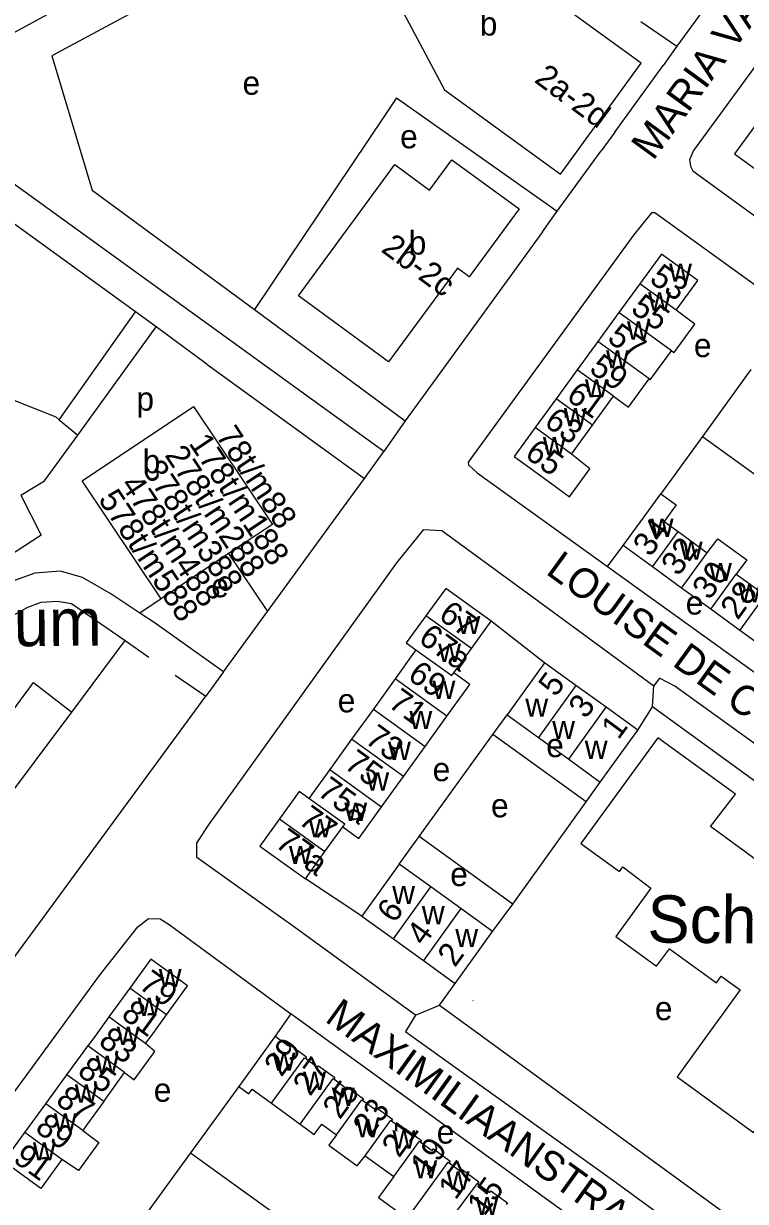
# Model space of a CAD drawing. Extents: x 159700 to 161346, y 381730 to 382922.
# Drawn here: x 159989.4 to 160111.3, y 382405.4 to 382604.4 of the extents above; entities that cross this region are included whole.
import ezdxf

# ---------------------------------------------------------------- set-up
doc = ezdxf.new("R2010")
doc.units = 0
for name, color, linetype in [('BLT_Basislijn', 7, 'Continuous'), ('BLT_Bebouwing', 7, 'Continuous'), ('BLT_Bebouwing_beschrifting', 7, 'Continuous'), ('BLT_Centroide', 7, 'Continuous'), ('BLT_Huisnummer', 7, 'Continuous'), ('BLT_Huisnummer_ tussenligend', 7, 'Continuous'), ('BLT_Huisnummer_reeks', 7, 'Continuous'), ('BLT_Onderverdeling_panden', 7, 'Continuous'), ('BLT_Straatnaam', 7, 'Continuous')]:
    doc.layers.add(name, color=color, linetype=linetype)

msp = doc.modelspace()

# ---------------------------------------------------------------- linework, layer by layer
at = {"layer": 'BLT_Basislijn'}
for p, q in [((160130.3, 382642.41), (160099.71, 382600.64)), ((160093.66, 382604.8), (160099.71, 382600.64)), ((160099.71, 382600.64), (160097.4, 382597.35)), ((160089.23, 382586.09), (160097.4, 382597.35)), ((160052.37, 382591.91), (160050.31, 382588.83)), ((160052.37, 382591.91), (160079.52, 382572.72)), ((160050.31, 382588.83), (160028.35, 382556.13)), ((160050.2, 382532.12), (159974.86, 382586.62)), ((160089.23, 382586.09), (160086.95, 382582.96)), ((160008.29, 382555.7), (159971.62, 382582.3)), ((160079.52, 382572.72), (160086.95, 382582.96)), ((160077.01, 382569.26), (160079.52, 382572.72)), ((160077.01, 382569.26), (160056.42, 382540.87)), ((160017.96, 382563.8), (160028.35, 382556.13)), ((160028.35, 382556.13), (160053.85, 382537.3)), ((159995.39, 382537.49), (160008.29, 382555.7)), ((160011.73, 382553.17), (160008.29, 382555.7)), ((159998.53, 382534.9), (160011.73, 382553.17)), ((160020.32, 382546.9), (160046.93, 382527.56)), ((160112.23, 382545.96), (160104.03, 382534.63)), ((160056.42, 382540.87), (160053.85, 382537.3)), ((159995.39, 382537.49), (159998.53, 382534.9)), ((160053.85, 382537.3), (160050.2, 382532.12)), ((160104.03, 382534.63), (160097.04, 382524.97)), ((160104.03, 382534.63), (160138.4, 382509.88)), ((160046.93, 382527.56), (160050.2, 382532.12)), ((160042.16, 382521.01), (160046.93, 382527.56)), ((160030.55, 382505.08), (160042.16, 382521.01)), ((160088, 382512.69), (160090.67, 382516.21)), ((160023.99, 382514.86), (160030.55, 382505.08)), ((160074.44, 382508.22), (160095.82, 382492.52)), ((160012.59, 382507.25), (160009.01, 382504.81)), ((160028.87, 382502.77), (160030.55, 382505.08)), ((160023.13, 382494.88), (160028.87, 382502.77)), ((160077.34, 382496.41), (160068.36, 382503.45)), ((159997.49, 382488.09), (160006.53, 382500.16)), ((160006.53, 382500.16), (160010.54, 382497.39)), ((160023.13, 382494.88), (160020.14, 382490.75)), ((160095.62, 382488.95), (160095.82, 382492.52)), ((159984.88, 382442.73), (160020.14, 382490.75)), ((160093.11, 382485.04), (160095.62, 382488.95)), ((159972.5, 382454.72), (159997.49, 382488.09)), ((160068.61, 382484.28), (160071.03, 382487.63)), ((160056.17, 382467.04), (160068.61, 382484.28)), ((160084.42, 382472.92), (160068.61, 382484.28)), ((160084.42, 382472.92), (160086.78, 382476.25)), ((160072.01, 382455.65), (160084.42, 382472.92)), ((160052.83, 382462.39), (160056.17, 382467.04)), ((160072.01, 382455.65), (160056.17, 382467.04)), ((160046.49, 382453.6), (160036.97, 382459.93)), ((160068.6, 382451.01), (160072.01, 382455.65)), ((160055.58, 382436.89), (160034.1, 382452.45)), ((160059.6, 382438.55), (160062.27, 382442.24)), ((160055.58, 382436.89), (160059.6, 382438.55)), ((160065.32, 382439.31), (160065.26, 382439.36)), ((160034.48, 382437.1), (160031.87, 382433.31)), ((160025.7, 382424.81), (160017.56, 382413.6)), ((160017.56, 382413.6), (160009.63, 382402.7)), ((160017.56, 382413.6), (160066.48, 382378.34))]:
    msp.add_line(p, q, dxfattribs=at)
for points in [[(160158.27, 382680.77), (160148.41, 382687.83), (160147.14, 382687.99), (160105.06, 382665.27), (160004.9, 382612.26), (159986.37, 382602.17), (159974.86, 382586.62)], [(160156.73, 382607.28), (160156.25, 382607.62), (160135.31, 382622.79), (160132.73, 382623.11), (160132.1, 382622.84), (160130.34, 382621.05), (160102.52, 382582.97), (160101.88, 382581.43), (160102.02, 382580.35), (160102.45, 382579.54), (160124.87, 382563.23)], [(160033.03, 382619.93), (159994.13, 382598.99), (160000.92, 382576.27), (160017.96, 382563.8)], [(160119.4, 382555.58), (160119.09, 382555.8), (160096, 382572.43), (160095.46, 382572.46), (160092.39, 382568.7), (160064.46, 382530.33), (160064.53, 382529.89), (160065.96, 382528.52), (160088, 382512.69)], [(160020.32, 382546.9), (160019.94, 382547.18), (160011.73, 382553.17)], [(159995.39, 382537.49), (159994.88, 382537.93), (159987.49, 382540.85), (159971.42, 382534.12)], [(159988.92, 382524.76), (159992.88, 382527.16), (159998.53, 382534.9)], [(159988.92, 382524.76), (159992.34, 382517.96), (159978.31, 382508.84)], [(159950.09, 382520.46), (159950.41, 382520.47), (159953.4, 382519.88), (159955.69, 382518.11), (159964.01, 382505.65), (159967.39, 382501.98), (159971.63, 382500.05), (159977.03, 382499.98), (159982.02, 382501.36), (159990.07, 382505.82), (159992.32, 382506.64), (159995.08, 382506.83), (159997.44, 382506.45), (160006.53, 382500.16)], [(160034.1, 382452.45), (160033.76, 382452.69), (160018.65, 382463.52), (160018.65, 382465.94), (160020.57, 382468.97), (160052.43, 382513.29), (160056.98, 382518.95), (160060, 382518.79), (160074.03, 382508.52), (160074.44, 382508.22)], [(160088, 382512.69), (160122.71, 382487.73)], [(160009.01, 382504.81), (160004.1, 382508.08), (159999.33, 382510.83), (159995.6, 382511.88), (159991.27, 382511.58), (159987.99, 382510.38), (159980.17, 382506.05)], [(160023.13, 382494.88), (160011.43, 382503.21), (160009.01, 382504.81)], [(160014.97, 382494.32), (160020.14, 382490.75)], [(159980.9, 382482.49), (159985.4, 382485.45), (159991.03, 382493.1), (159997.49, 382488.09)], [(160055.58, 382436.89), (160053.86, 382434.1), (160054.93, 382433.33), (160088.85, 382409.04), (160123.19, 382383.92), (160125.73, 382383.39), (160128.86, 382384.06), (160133.46, 382389.51), (160165.14, 382433.33), (160167.65, 382436.8), (160168.16, 382438.78), (160167.81, 382441.67), (160167.07, 382442.79), (160165.27, 382444.61), (160155.77, 382451.87), (160099.41, 382492.45), (160096.79, 382493.83), (160095.82, 382492.52)], [(160059.6, 382438.55), (160125.46, 382390.57), (160127.6, 382390.97), (160163.12, 382439.91), (160095.62, 382488.95)], [(160001.68, 382391.75), (160001.38, 382391.97), (159978.05, 382408.94), (159977.91, 382409.89), (159978.23, 382410.9), (159994.7, 382433.33), (160002.19, 382443.55), (160008.66, 382451.78), (160010.48, 382453.23), (160012.45, 382453.12), (160013.98, 382452.17), (160034.05, 382437.41), (160034.48, 382437.1)], [(160083.45, 382401.6), (160039.67, 382433.33), (160034.48, 382437.1)]]:
    msp.add_lwpolyline(points, dxfattribs=at)
at = {"layer": 'BLT_Bebouwing'}
for p, q in [((160093.46, 382560.45), (160089.94, 382555.61)), ((160089.94, 382555.61), (160086.36, 382550.69)), ((160086.36, 382550.69), (160082.91, 382545.94)), ((160082.91, 382545.94), (160079.36, 382541.05)), ((160079.36, 382541.05), (160075.8, 382536.16)), ((160085.49, 382536.59), (160089.04, 382541.48)), ((160018.07, 382539.74), (160031.39, 382519.81)), ((160081.93, 382531.7), (160085.49, 382536.59)), ((160031.39, 382519.81), (160023.99, 382514.86)), ((160099.92, 382518.59), (160104.85, 382515)), ((160095.6, 382512.63), (160090.67, 382516.21)), ((160023.99, 382514.86), (160012.59, 382507.25)), ((160100.53, 382509.05), (160095.6, 382512.63)), ((160109.77, 382511.42), (160114.7, 382507.84)), ((160105.45, 382505.47), (160100.53, 382509.05)), ((160110.38, 382501.89), (160105.45, 382505.47)), ((160065.02, 382498.83), (160068.36, 382503.45)), ((160112.98, 382500), (160110.38, 382501.89)), ((160055.63, 382498.62), (160052.13, 382493.71)), ((160062.04, 382494.7), (160065.02, 382498.83)), ((160077.34, 382496.41), (160071.03, 382487.63)), ((160082.68, 382492.57), (160077.34, 382496.41)), ((160052.13, 382493.71), (160048.45, 382488.6)), ((160087.77, 382488.89), (160082.68, 382492.57)), ((160048.45, 382488.6), (160044.77, 382483.5)), ((160093.11, 382485.04), (160087.77, 382488.89)), ((160057.2, 382482.29), (160060.88, 382487.4)), ((160071.03, 382487.63), (160076.37, 382483.79)), ((160086.78, 382476.25), (160093.11, 382485.04)), ((160044.77, 382483.5), (160041.08, 382478.39)), ((160053.52, 382477.2), (160057.2, 382482.29)), ((160076.37, 382483.79), (160081.47, 382480.11)), ((160041.08, 382478.39), (160037.55, 382473.49)), ((160081.47, 382480.11), (160086.78, 382476.25)), ((160049.83, 382472.09), (160053.52, 382477.2)), ((160040.28, 382464.5), (160043.29, 382468.68)), ((160036.97, 382459.93), (160040.28, 382464.5)), ((160052.83, 382462.39), (160046.49, 382453.6)), ((160058.18, 382458.53), (160052.83, 382462.39)), ((160063.22, 382454.89), (160058.18, 382458.53)), ((160068.6, 382451.01), (160063.22, 382454.89)), ((160046.49, 382453.6), (160051.83, 382449.76)), ((160062.27, 382442.24), (160068.6, 382451.01)), ((160051.83, 382449.76), (160056.91, 382446.1)), ((160056.91, 382446.1), (160062.27, 382442.24)), ((160007.3, 382441.45), (160003.76, 382436.56)), ((159993.13, 382421.89), (159996.68, 382426.78)), ((160002.89, 382422.27), (160006.43, 382427.16)), ((159989.58, 382417.01), (159993.13, 382421.89))]:
    msp.add_line(p, q, dxfattribs=at)
for points in [[(160043.33, 382625.44), (160060.45, 382593.26), (160080.07, 382579), (160093.7, 382597.77), (160073.47, 382612.45), (160071.28, 382616.55)], [(160113.02, 382587.3), (160109.47, 382582.42), (160115.64, 382577.93), (160119.19, 382582.82)], [(160073.06, 382573.11), (160064.64, 382561.65), (160062.65, 382563.12), (160050.98, 382547.25), (160035.78, 382558.42), (160052.08, 382580.61), (160057.95, 382576.29), (160061.73, 382581.44), (160073.06, 382573.11)], [(160099.59, 382555.99), (160103.25, 382561.03), (160097.12, 382565.48), (160093.46, 382560.45)], [(160098.82, 382549.15), (160099.27, 382548.83), (160102.78, 382553.66), (160099.59, 382555.99)], [(160095.04, 382544.38), (160095.24, 382544.23), (160098.82, 382549.15)], [(160089.04, 382541.48), (160091.57, 382539.6), (160095.04, 382544.38)], [(160012.59, 382507.25), (159999.27, 382527.18), (160018.07, 382539.74)], [(160075.8, 382536.16), (160072.25, 382531.27), (160078.38, 382526.82), (160081.6, 382524.48), (160085.04, 382529.21), (160081.93, 382531.7)], [(160090.67, 382516.21), (160093.61, 382520.26), (160097.04, 382524.97)], [(160097.04, 382524.97), (160099.6, 382523.11), (160097.56, 382520.3), (160099.92, 382518.59)], [(160104.85, 382515), (160106.64, 382517.36), (160111.53, 382513.8), (160109.77, 382511.42)], [(160068.36, 382503.45), (160060.68, 382508.99), (160057.34, 382504.37)], [(160057.34, 382504.37), (160054.02, 382499.77), (160055.63, 382498.62)], [(160060.88, 382487.4), (160064.74, 382492.74), (160062.04, 382494.7)], [(160096.52, 382483.76), (160083.49, 382465.9)], [(160134.12, 382444.61), (160135.63, 382446.67), (160133.44, 382448.19), (160128.42, 382451.93), (160127.9, 382455.28), (160123.7, 382458.35), (160120.34, 382457.82), (160105.39, 382468.74), (160109.61, 382474.22), (160096.52, 382483.76)], [(160037.55, 382473.49), (160035.91, 382474.67), (160032.6, 382470.07)], [(160043.29, 382468.68), (160045.98, 382466.74), (160049.83, 382472.09)], [(160032.6, 382470.07), (160029.28, 382465.45), (160036.97, 382459.93)], [(160083.49, 382465.9), (160090.03, 382461.12), (160090.62, 382461.94), (160095.34, 382458.32), (160089.4, 382450.14), (160096.3, 382445.13)], [(160013.53, 382436.93), (160017.07, 382441.81), (160010.83, 382446.34), (160007.3, 382441.45)], [(160096.3, 382445.13), (160098.46, 382448.1), (160106.41, 382442.33), (160107.23, 382443.47), (160110.43, 382441.15), (160104.75, 382433.33), (160099.75, 382426.44)], [(160099.75, 382426.44), (160112.67, 382417.06), (160113.45, 382418.13), (160116.31, 382416.06), (160115.54, 382415), (160128.43, 382405.64), (160137.78, 382418.52), (160136.7, 382419.3), (160138.81, 382422.22), (160139.83, 382421.48), (160148.43, 382433.33), (160149.15, 382434.32), (160136.32, 382443.63), (160135.58, 382442.61), (160133.84, 382443.87), (160134.28, 382444.49), (160134.12, 382444.61)], [(160003.76, 382436.56), (160001.43, 382433.33), (160000.22, 382431.66)], [(160009.98, 382432.05), (160010.92, 382433.33), (160013.53, 382436.93)], [(160031.87, 382433.31), (160029.1, 382429.5), (160025.7, 382424.81)], [(160031.87, 382433.31), (160034.14, 382431.66), (160034.31, 382431.9), (160037.14, 382429.84), (160036.96, 382429.59)], [(159996.68, 382426.78), (160000.02, 382431.38), (160000.22, 382431.66)], [(160006.43, 382427.16), (160008.06, 382425.95), (160011.51, 382430.72), (160009.98, 382432.05)], [(160036.96, 382429.59), (160039, 382428.1), (160039.17, 382428.33), (160041.93, 382426.32), (160041.76, 382426.08)], [(160025.7, 382424.81), (160027.41, 382423.57), (160027.99, 382424.35), (160031.23, 382421.98)], [(160041.76, 382426.08), (160043.86, 382424.55), (160044.02, 382424.77), (160046.81, 382422.74), (160046.62, 382422.49)], [(160046.62, 382422.49), (160048.7, 382420.98), (160048.91, 382421.27), (160051.66, 382419.27), (160051.49, 382419.03)], [(160002.89, 382422.27), (160000, 382418.3), (159999.34, 382417.39)], [(160031.23, 382421.98), (160036.07, 382418.43)], [(160051.49, 382419.03), (160053.62, 382417.47), (160053.8, 382417.73), (160056.61, 382415.68), (160056.42, 382415.42)], [(159995.81, 382412.49), (159992.27, 382407.6), (159986.04, 382412.12), (159989.58, 382417.01)], [(159999.34, 382417.39), (160002.05, 382415.32), (159998.63, 382410.6), (159995.81, 382412.49)], [(160036.07, 382418.43), (160038.45, 382416.7), (160039.75, 382418.45), (160042.2, 382416.66)], [(160042.2, 382416.66), (160040.9, 382414.9), (160045.73, 382411.38), (160047.04, 382413.12)], [(160056.42, 382415.42), (160058.41, 382413.97), (160058.63, 382414.26), (160061.45, 382412.21), (160061.24, 382411.93)], [(160047.04, 382413.12), (160051.9, 382409.59)], [(160061.24, 382411.93), (160063.25, 382410.47), (160063.46, 382410.76), (160066.28, 382408.7), (160066.07, 382408.41)], [(160051.9, 382409.59), (160049.31, 382406.05), (160054.12, 382402.54), (160055.38, 382404.17)], [(160066.07, 382408.41), (160068.12, 382406.92), (160068.31, 382407.18), (160071.12, 382405.14), (160070.91, 382404.85)]]:
    msp.add_lwpolyline(points, dxfattribs=at)
at = {"layer": 'BLT_Onderverdeling_panden'}
for p, q in [((160099.59, 382555.99), (160093.46, 382560.45)), ((160098.82, 382549.15), (160089.94, 382555.61)), ((160095.04, 382544.38), (160086.36, 382550.69)), ((160089.04, 382541.48), (160082.91, 382545.94)), ((160085.49, 382536.59), (160079.36, 382541.05)), ((160081.93, 382531.7), (160075.8, 382536.16)), ((160095.6, 382512.63), (160099.92, 382518.59)), ((160100.53, 382509.05), (160104.85, 382515)), ((160105.45, 382505.47), (160109.77, 382511.42)), ((160110.38, 382501.89), (160114.7, 382507.84)), ((160065.02, 382498.83), (160057.34, 382504.37)), ((160060.88, 382487.4), (160052.13, 382493.71)), ((160082.68, 382492.57), (160076.37, 382483.79)), ((160048.45, 382488.6), (160057.2, 382482.29)), ((160081.47, 382480.11), (160087.77, 382488.89)), ((160053.52, 382477.2), (160044.77, 382483.5)), ((160041.08, 382478.39), (160049.83, 382472.09)), ((160032.6, 382470.07), (160040.28, 382464.5)), ((160051.83, 382449.76), (160058.18, 382458.53)), ((160063.22, 382454.89), (160056.91, 382446.1)), ((160013.53, 382436.93), (160007.3, 382441.45)), ((160006.43, 382427.16), (160000.22, 382431.66)), ((160002.89, 382422.27), (159996.68, 382426.78)), ((159999.34, 382417.39), (159993.13, 382421.89)), ((159995.81, 382412.49), (159989.58, 382417.01)), ((160061.6, 382402.52), (160066.07, 382408.41))]:
    msp.add_line(p, q, dxfattribs=at)
for points in [[(160055.63, 382498.62), (160061.73, 382494.27), (160062.04, 382494.7)], [(160043.29, 382468.68), (160043.62, 382469.14), (160037.55, 382473.49)], [(160009.98, 382432.05), (160008.2, 382433.33), (160003.76, 382436.56)], [(160031.23, 382421.98), (160036.82, 382429.68), (160036.96, 382429.59)], [(160036.07, 382418.43), (160041.67, 382426.15), (160041.76, 382426.08)], [(160042.2, 382416.66), (160046.5, 382422.58), (160046.62, 382422.49)], [(160047.04, 382413.12), (160051.39, 382419.1), (160051.49, 382419.03)], [(160051.9, 382409.59), (160056.24, 382415.56), (160056.42, 382415.42)], [(160055.38, 382404.17), (160061.09, 382412.04), (160061.24, 382411.93)]]:
    msp.add_lwpolyline(points, dxfattribs=at)

# ---------------------------------------------------------------- texts
at = {"layer": 'BLT_Bebouwing_beschrifting'}
for s, rotation, p in [('Woonzorgcentrum', 0.5505, (159915.19, 382498.5)), ('School', 359.4874, (160094.73, 382449.15))]:
    msp.add_text(s, height=8, rotation=rotation, dxfattribs=at).set_placement(p)
at = {"layer": 'BLT_Centroide'}
for s, p in [('b', (160066.43, 382602.42)), ('e', (160026.35, 382592.41)), ('e', (160052.97, 382583.36)), ('b', (160054.42, 382565.41)), ('w', (160098.41, 382560.81)), ('w', (160094.86, 382555.94)), ('w', (160091.3, 382551.03)), ('e', (160102.6, 382548.07)), ('w', (160087.75, 382546.16)), ('w', (160084.2, 382541.25)), ('p', (160008.42, 382539.03)), ('w', (160080.64, 382536.38)), ('w', (160077.09, 382531.5)), ('b', (160009.48, 382528.46)), ('w', (160095.3, 382517.7)), ('w', (160100.22, 382513.83)), ('w', (160105.16, 382510.23)), ('e', (160021.07, 382507.49)), ('w', (160110.08, 382506.66)), ('e', (160101.22, 382504.57)), ('w', (160062.66, 382501.27)), ('w', (160059.4, 382496.55)), ('w', (160058.44, 382490.31)), ('e', (160042.43, 382488.04)), ('w', (160074.12, 382487.29)), ('w', (160054.54, 382485.22)), ('w', (160078.66, 382483.53)), ('w', (160050.92, 382479.99)), ('e', (160077.65, 382480.47)), ('w', (160084.16, 382480.18)), ('e', (160058.47, 382476.41)), ('w', (160047.25, 382474.81)), ('w', (160043.54, 382469.68)), ('e', (160068.33, 382470.3)), ('w', (160037.53, 382466.93)), ('w', (160034.19, 382462.39)), ('e', (160061.44, 382458.68)), ('w', (160051.63, 382455.65)), ('w', (160056.64, 382452.22)), ('w', (160062.29, 382448.36)), ('w', (160012.19, 382441.62)), ('w', (160008.64, 382436.75)), ('e', (160096.01, 382436.02)), ('w', (160005.1, 382431.84)), ('w', (160031.42, 382427.47)), ('w', (160001.55, 382426.97)), ('w', (160036.58, 382424.23)), ('w', (159998.01, 382422.09)), ('e', (160011.35, 382422.23)), ('w', (160041.44, 382421.52)), ('w', (159994.46, 382417.19)), ('w', (160045.56, 382416.22)), ('w', (160051.67, 382414.33)), ('e', (160059.15, 382415.16)), ('w', (159990.92, 382412.31)), ('w', (160055.38, 382409.27)), ('w', (160060.83, 382407.38)), ('w', (160065.73, 382403.09))]:
    msp.add_text(s, height=4, dxfattribs=at).set_placement(p)
at = {"layer": 'BLT_Huisnummer'}
for s, rotation, p in [('53', 323.9843, (160094.9, 382560.88)), ('57', 323.9843, (160087.77, 382550.86)), ('61', 323.9826, (160080.85, 382541.03)), ('65', 323.9826, (160073.84, 382531.28)), ('34', 53.9715, (160095.24, 382514.15)), ('30', 53.9732, (160105.25, 382506.86)), ('67', 324.0859, (160059.26, 382503.97)), ('67a', 324.0859, (160055.87, 382500.05)), ('69', 324.0859, (160054.04, 382493.82)), ('5', 53.7174, (160079.25, 382490.48)), ('1', 53.6802, (160089.85, 382483.27)), ('75', 324.0859, (160043.32, 382478.79)), ('75a', 324.0859, (160038.79, 382474.2)), ('77', 324.0876, (160035.57, 382469.38)), ('77a', 324.0876, (160031.64, 382465.5)), ('6', 54.0835, (160052, 382452.24)), ('2', 54.0788, (160062.23, 382444.81)), ('79', 324.0632, (160008.62, 382441.55)), ('83', 324.0576, (160001.81, 382431.97)), ('29', 53.9296, (160032.92, 382426.28)), ('87', 324.0651, (159994.58, 382422.04)), ('23', 53.9305, (160047.9, 382416.07)), ('91', 324.029, (159987.4, 382412.2)), ('19', 53.9335, (160057.6, 382409.46)), ('15', 53.9415, (160067.2, 382402.76))]:
    msp.add_text(s, height=4, rotation=rotation, dxfattribs=at).set_placement(p)
at = {"layer": 'BLT_Huisnummer_ tussenligend'}
for s, rotation, p in [('55', 323.9843, (160091.74, 382555.81)), ('59', 323.9843, (160084.72, 382545.68)), ('63', 323.9826, (160077.11, 382536.65)), ('32', 53.9732, (160099.99, 382510.89)), ('28', 53.9705, (160110.01, 382503.5)), ('71', 324.0859, (160050.76, 382489.14)), ('3', 53.6802, (160084.34, 382486.79)), ('73', 324.0859, (160046.83, 382483.03)), ('4', 54.0788, (160056.99, 382448.4)), ('81', 324.0632, (160005.65, 382436.54)), ('85', 324.0576, (159998.25, 382426.94)), ('27', 53.9367, (160037.77, 382423.03)), ('25', 53.9367, (160042.79, 382419.08)), ('89', 324.0651, (159991.1, 382417.36)), ('21', 53.9305, (160052.78, 382412.6)), ('17', 53.9335, (160062.34, 382405.49))]:
    msp.add_text(s, height=4, rotation=rotation, dxfattribs=at).set_placement(p)
at = {"layer": 'BLT_Huisnummer_reeks'}
for s, rotation, p in [('2a-2d', 323.6797, (160075.46, 382594.67)), ('2b-2c', 323.6797, (160049.58, 382566.01)), ('78t/m88', 303.6386, (160021.75, 382534.76)), ('178t/m188', 303.6386, (160017.17, 382533.52)), ('278t/m288', 303.6386, (160013.1, 382531.51)), ('378t/m388', 303.6386, (160009.35, 382529.02)), ('478t/m488', 303.6386, (160005.61, 382526.53)), ('578t/m588', 303.6386, (160001.86, 382524.03))]:
    msp.add_text(s, height=4, rotation=rotation, dxfattribs=at).set_placement(p)
at = {"layer": 'BLT_Straatnaam'}
for s, rotation, p in [('MARIA VAN BOURGONDIELAAN', 53.8448, (160095.72, 382581.14)), ('LOUISE DE COLIGNYSTRAAT', 324.0647, (160077.4, 382511.56)), ('MAXIMILIAANSTRAAT', 324.2059, (160040.08, 382435.92))]:
    msp.add_text(s, height=5, rotation=rotation, dxfattribs=at).set_placement(p)

doc.saveas('drawing.dxf')
